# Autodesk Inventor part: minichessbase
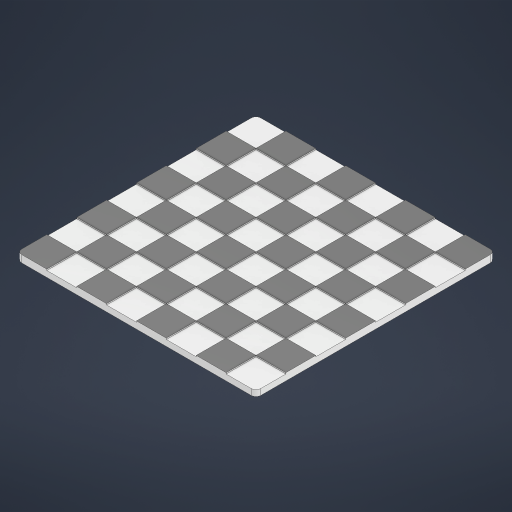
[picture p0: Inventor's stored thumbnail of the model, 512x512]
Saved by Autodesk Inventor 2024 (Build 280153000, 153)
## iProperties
Created: 2025-07
Part Number: minichessbase
Material: ABS Plastic
Document SubType Name: Modeling
Designer: acer
Density: 1.06 g/cm^3
Appearance: Smooth - White
Author: acer
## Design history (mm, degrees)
sketch "Sketch1"
  geometry: L1 (100, 100)-(-100, 100); L2 (-100, 100)-(-100, -100); L3 (-100, -100)-(100, -100); L4 (100, -100)-(100, 100); L5 (100, 100)-(-100, -100); L6 (-100, 100)-(100, -100); 1 further point
  constraints: 12 end point, 2 midpoint, 2 parallel, 1 horizontal, 1 perpendicular
  dimensions: "d0" = 200 distance of L3.end L2.end; "d1" = 200 distance of L2.end L1.end
extrude "Extrusion1" new body sketch "Sketch1" distance "d2" = 5; taper "d3" = 0 deg
sketch "Sketch2"
  geometry: L1 (-100, 100)-(-100, -100) reference; L2 (-100, -100)-(-75, -100); L3 (-75, -100)-(-75, -75); L4 (-75, -75)-(-100, -75); L5 (-100, -75)-(-100, -100); L6 (100, 100)-(-100, 100) reference; L7 (-100, -100)-(100, -100); L8 (100, -100)-(100, 100); L9 (100, 100)-(-100, 100); L10 (-100, 100)-(-100, -100); L11 (-75, -50)-(-100, -50); L12 (-75, -75)-(-75, -50); L13 (-100, -50)-(-100, -75); L14 (-100, -75)-(-75, -75); L15 (-75, -25)-(-100, -25); L16 (-75, -50)-(-75, -25); L17 (-100, -25)-(-100, -50); L18 (-100, -50)-(-75, -50); L19 (-75, 0)-(-100, 0); L20 (-75, -25)-(-75, 0); L21 (-100, 0)-(-100, -25); L22 (-100, -25)-(-75, -25); L23 (-75, 25)-(-100, 25); L24 (-75, 0)-(-75, 25); L25 (-100, 25)-(-100, 0); L26 (-100, 0)-(-75, 0); L27 (-75, 50)-(-100, 50); L28 (-75, 25)-(-75, 50); L29 (-100, 50)-(-100, 25); L30 (-100, 25)-(-75, 25); L31 (-75, 75)-(-100, 75); L32 (-75, 50)-(-75, 75); L33 (-100, 75)-(-100, 50); L34 (-100, 50)-(-75, 50); L35 (-75, 100)-(-100, 100); L36 (-75, 75)-(-75, 100); L37 (-100, 100)-(-100, 75); L38 (-100, 75)-(-75, 75); L39 (-50, -75)-(-75, -75); L40 (-50, -100)-(-50, -75); L41 (-75, -75)-(-75, -100); L42 (-75, -100)-(-50, -100); L43 (-50, -50)-(-75, -50); L44 (-50, -75)-(-50, -50); L45 (-75, -50)-(-75, -75); L46 (-75, -75)-(-50, -75); L47 (-50, -25)-(-75, -25); L48 (-50, -50)-(-50, -25); L49 (-75, -25)-(-75, -50); L50 (-75, -50)-(-50, -50); L51 (-50, 0)-(-75, 0); L52 (-50, -25)-(-50, 0); L53 (-75, 0)-(-75, -25); L54 (-75, -25)-(-50, -25); L55 (-50, 25)-(-75, 25); L56 (-50, 0)-(-50, 25); L57 (-75, 25)-(-75, 0); L58 (-75, 0)-(-50, 0); L59 (-50, 50)-(-75, 50); L60 (-50, 25)-(-50, 50); L61 (-75, 50)-(-75, 25); L62 (-75, 25)-(-50, 25); L63 (-50, 75)-(-75, 75); L64 (-50, 50)-(-50, 75)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; 273 further points
  constraints: 520 end point, 4 parallel, 3 horizontal, 2 perpendicular, 1 vertical, 504 other
  dimensions: "d4" = 25 distance of L4.end L3.end; "d5" = 25 distance of L3.end L2.end; "d8" = 25 distance of L3.end L11.start; "d11" = 25 distance of L3.end L39.start
extrude "Extrusion2" join sketch "Sketch2" distance "d14" = 1; taper "d15" = 0 deg
fillet "Fillet1" dims "d16" = 4
body "Solid1"
